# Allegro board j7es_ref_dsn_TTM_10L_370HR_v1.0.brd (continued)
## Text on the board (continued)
User.45: J3 | E | U101 | R99 | R178 | R13 | C210 | U30 | D1 | C490 | R155 | Y6 | R146 | C492 | C486 | J5 | J1 | TP90 | TP91 | J12 | FL29 | C570 | J13 | C68 | R204 | G | F | B | H | C236 | A | C244 | J2 | R234 | C411 | FL28 | C | C273 | C284 | C523 | FL21 | C295 | FL24 | C348 | FL22 | C313 | C369 | TP89 | TP88 | J9 | FL23 | C296 | FL25 | C314 | C349 | C370 | J8 | J4 | C233 | R454 | R515 | C408 | C409 | C203 | R491 | R492 | R270 | C353 | C367 | R465 | C360 | R282 | C446 | R284 | C361 | C368 | C377 | R521 | R95 | U22 | C354 | C371 | R283 | C358 | C451 | C425 | C208 | R169 | R171 | C204 | C355 | R476 | U107 | R276 | C551 | C359 | C415 | C509 | R467 | R279 | R272 | C496 | R277 | C414 | U102 | R278 | R466 | R522 | R235 | R239 | R509 | R230 | R227 | R273 | C338 | C500 | C502 | C389 | R510 | R274 | R275 | C287 | C301 | C323 | C345 | C288 | C289 | R525 | C393 | R524 | C290 | C388 | C384 | C565 | R516 | R232 | R198 | C317 | C308 | C304 | C375 | C381 | C307 | C383 | C276 | C282 | C286 | C319 | C453 | C450 | C292 | C305 | C309 | C310 | C434 | C396 | C277 | C283 | C291 | R264 | C385 | C480 | C311 | C299 | C278 | R247 | R205 | R219 | R220 | R221 | R222 | R262 | C462 | C460 | C461 | C443 | R229 | C321 | C329 | C335 | C342 | R281 | R226 | R224 | C407 | R214 | R255 | R206 | C445 | R245 | R250 | R244 | R249 | R251 | C322 | C330 | C336 | C343 | R223 | R240 | C331 | C337 | C344 | C315 | U23 | U25 | C274 | R203 | R213 | C412 | C533 | C424 | C532 | R207 | C467 | C466 | R188 | R189 | R190 | R191 | R193 | R195 | C350 | C326 | C531 | C356 | C363 | C536 | C318 | C376 | R194 | R196 | R197 | R199 | R200 | R212 | C357 | C364 | C413 | C327 | U24 | C365 | R253 | C542 | C328 | C334 | C333 | C449 | C366 | C569 | C568 | C567 | R523 | R287 | R288 | R233 | R210 | C306 | C427 | C554 | C211 | C485 | R160 | R102 | C491 | C69 | R242 | R243 | C571 | C562 | R218 | FL18 | R217 | R209 | C242 | R215 | C243 | FL16 | FL19 | C402 | C403 | R237 | FL26 | C410 | C245 | C237 | R238 | C404 | C405 | FL17 | FL20 | FL27 | C238 | C246 | TP57 | C247 | C239 | TP61 | TP58 | TP62 | TP59 | TP60 | R176 | R252 | C527 | R225 | C522 | C519 | C524 | TP50 | TP46 | TP47 | C528 | TP48 | TP51 | TP49 | TP54 | TP52 | TP53 | TP56 | TP55 | C229 | C556 | C232 | C230 | C228 | R463 | C442 | R464 | C549 | C550 | C558 | R462 | C555 | R485 | R269 | R486 | R170 | C494 | R517 | R519 | C482 | C566 | C362 | C380 | C503 | C382 | R493 | C372 | C416 | C505 | C417 | C510 | C418 | C506 | C557 | C419 | C511 | C420 | C498 | C421 | C497 | C422 | C508 | C423 | C373 | C387 | C391 | R180 | C394 | C312 | C395 | C374 | C386 | C216 | C261 | C392 | C217 | C397 | C262 | C252 | C302 | C253 | C263 | C398 | C258 | C218 | C264 | C303 | C399 | C219 | C265 | C255 | C400 | C266 | C254 | C341 | C267 | C256 | C268 | R228 | C257 | C269 | C259 | C270 | C271 | R192 | C390 | C430 | C298 | C220 | C294 | C212 | C221 | C431 | C279 | C213 | C432 | R236 | C435 | C439 | C436 | C441 | C433 | C297 | C280 | C222 | C223 | C275 | C285 | C224 | C214 | C225 | C293 | C215 | C281 | C226 | C227 | R201 | R254 | R241 | R216 | R202 | C444 | R208 | C401 | C406 | C316 | C516 | C339 | C517 | C537 | C378 | C332 | C346 | C300 | C530 | C535 | C324 | C437 | C428 | C452 | C351 | C438 | R495 | C429 | C440 | C320 | C340 | C352 | C540 | C379 | C325 | BOARD NAME: | J721EX SOM 941x PMIC BRD | REV: E5 | DATE: 03/06/2019 | DESCRIPTION: | SHEET | ASSEMBLY TOP | OF | 23 | PROC078 | BOTTOM ASSEMBLY | ASSEMBLY BOTTOM | SCALE: 1 | NOTES: | - DRILL SIZES LISTED IN LEGEND | ARE CONSIDERED FINISHED. | - VENDOR IS REQUIRED TO SELECT | TOOLING FOR OVERDRILLING. | - LEGEND DOES NOT SPECIFY DEPTH | INTO ADJACENT DIELECTRIC LAYER. | START | L1 | FIGURE | L16 | TARGET | L10 | SIZE | 7.98 | 7.99 | L11 | 7.96 | L4 | BACKDRILL: TOP to L10-SIGNAL | ALL UNITS ARE IN MILS | BACKDRILL: BOTTOM to L11-GND4 | MUST CUT | L9 | TOLERANCE | +3.0/-0.0 | +3.0/-3.0 | BACKDRILL: BOTTOM to L4-GND2 | L12 | L5 | PLATED | MUST NOT CUT | L3 | QTY | 64 | 128 | 18 | 8.0 | 10.0 | 12.0 | 36.0 | 40.0 | 34.0 | 42.0 | 58.0 | 66.0 | 108.0 | 250.0 | DRILL CHART: TOP to BOTTOM | +2.0/-2.0 | +1.0/-1.0 | NON-PLATED | 2961 | 984 | 57 | 3 | 6 | 2 | 12 | 4 | TEXAS INSTRUMENTS | 6 - Provide serial numbers to the assembled boards for identification. | 7 - The assembled board are wrapped in ESD Covers(individual) and packed securely before shipment. | ASSEMBLY NOTES:- | 1 - All MSL components should be baked as per JEDEC standard. | 2 - PCB should be baked at 120 degree for 8 hours. | 3 - Board assembly must comply with workmanship standards IPC-A-610 Class 2, unless otherwise specified. | 4 - These assemblies are ESD sensitive, ESD precautions shall be observed. | 5 - These assemblies must be clean and free from flux and all contaminants. Use of no clean flux is not acceptable. | PROC078 E5 ASSEMBLY TOP | PROC078 E5 ASSEMBLY BOTTOM | J721EX SOM 941x PMIC BOTTOM ASSEMBLY REV.E5
